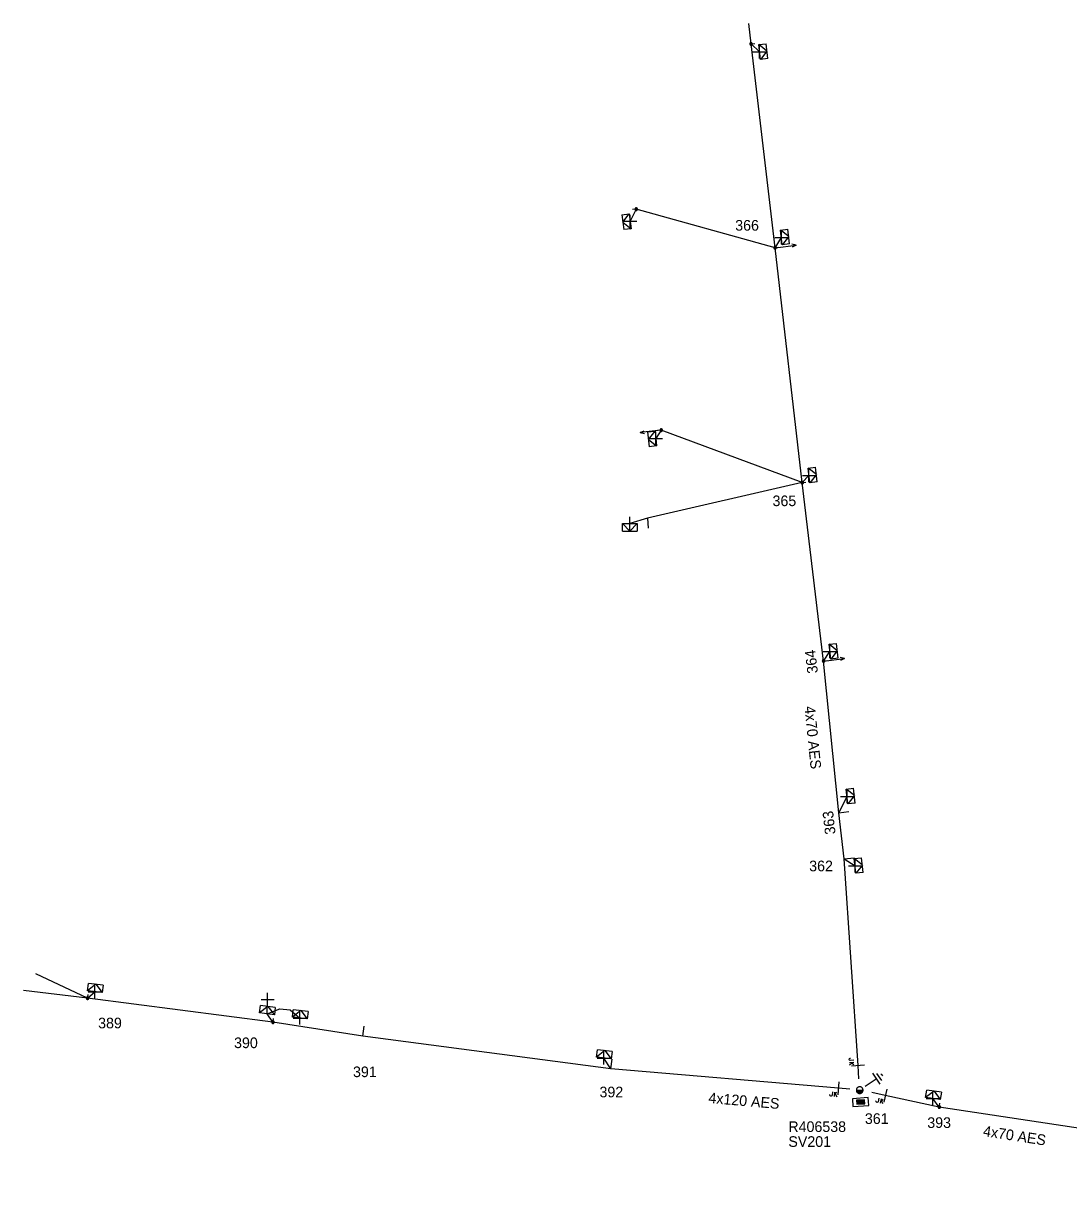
# Model space of a CAD drawing. Extents: x -540466 to -537383, y -1184038 to -1179972.
# Drawn here: x -539419.3 to -539321, y -1180540.1 to -1180429.3 of the extents above; entities that cross this region are included whole.
import ezdxf

# ---------------------------------------------------------------- set-up
doc = ezdxf.new("R2010")
doc.units = 0
for name, color, linetype in [('Vrstva 1', 7, 'Continuous'), ('Vrstva 13', 7, 'Continuous'), ('Vrstva 14', 7, 'Continuous'), ('Vrstva 15', 7, 'Continuous'), ('Vrstva 18', 7, 'Continuous'), ('Vrstva 2', 7, 'Continuous'), ('Vrstva 28', 7, 'Continuous'), ('Vrstva 29', 7, 'Continuous'), ('Vrstva 30', 7, 'Continuous'), ('Vrstva 31', 7, 'Continuous'), ('Vrstva 34', 7, 'Continuous'), ('Vrstva 50', 7, 'Continuous'), ('Vrstva 51', 7, 'Continuous'), ('Vrstva 54', 7, 'Continuous'), ('Vrstva 59', 7, 'Continuous'), ('Vrstva 8', 7, 'Continuous'), ('Vrstva 9', 7, 'Continuous')]:
    doc.layers.add(name, color=color, linetype=linetype)

# ---------------------------------------------------------------- blocks, each defined once
blk = doc.blocks.new('NN440')
at = {"layer": 'Vrstva 2'}
for points in [[(0.63, 0), (0.63, 0.06), (0.62, 0.13), (0.6, 0.19), (0.58, 0.25), (0.55, 0.31), (0.51, 0.37), (0.47, 0.42), (0.42, 0.46), (0.37, 0.51), (0.32, 0.54), (0.26, 0.57), (0.2, 0.59), (0.13, 0.61), (0.07, 0.62), (0, 0.63), (-0.06, 0.62), (-0.13, 0.61), (-0.19, 0.59), (-0.26, 0.57), (-0.31, 0.54), (-0.37, 0.51), (-0.42, 0.46), (-0.47, 0.42), (-0.51, 0.37), (-0.54, 0.31), (-0.57, 0.25), (-0.6, 0.19), (-0.62, 0.13), (-0.63, 0.06), (-0.63, 0), (-0.63, -0.07), (-0.62, -0.14), (-0.6, -0.2), (-0.57, -0.26), (-0.54, -0.32), (-0.51, -0.37), (-0.47, -0.43), (-0.42, -0.47), (-0.37, -0.51), (-0.31, -0.55), (-0.26, -0.58), (-0.19, -0.6), (-0.13, -0.62), (-0.06, -0.63), (0, -0.63), (0.07, -0.63), (0.13, -0.62), (0.2, -0.6), (0.26, -0.58), (0.32, -0.55), (0.37, -0.51), (0.42, -0.47), (0.47, -0.43), (0.51, -0.37), (0.55, -0.32), (0.58, -0.26), (0.6, -0.2), (0.62, -0.14), (0.63, -0.07), (0.63, 0)], [(-0.63, 0), (0.63, 0)], [(-0.6, -0.18), (0.57, -0.18)], [(-0.51, -0.32), (0.5, -0.32)], [(-0.37, -0.47), (0.35, -0.47)]]:
    blk.add_lwpolyline(points, dxfattribs=at)
blk = doc.blocks.new('NN560')
at = {"layer": 'Vrstva 2'}
for points in [[(2, 0), (1.59, 0.14)], [(0, 0), (2, 0)], [(2, 0), (1.59, -0.13)]]:
    blk.add_lwpolyline(points, dxfattribs=at)
blk = doc.blocks.new('NN840')
at = {"layer": 'Vrstva 15'}
for points in [[(0, 0.62), (0, -0.63)], [(-0.75, -0.71), (-0.75, -0.66)], [(-0.73, -0.76), (-0.75, -0.71)], [(-0.66, -0.8), (-0.73, -0.76)], [(-0.63, -0.8), (-0.66, -0.8)], [(-0.56, -0.76), (-0.63, -0.8)], [(-0.54, -0.71), (-0.56, -0.76)], [(-0.54, -0.38), (-0.54, -0.71)], [(-0.33, -0.38), (-0.33, -0.8)], [(-0.33, -0.64), (-0.13, -0.38)], [(-0.26, -0.56), (-0.09, -0.8)]]:
    blk.add_lwpolyline(points, dxfattribs=at)
blk = doc.blocks.new('NN800')
at = {"layer": 'Vrstva 1'}
for points in [[(-0.44, 0.44), (0.44, -0.44)], [(-0.44, -0.44), (0.44, 0.44)]]:
    blk.add_lwpolyline(points, dxfattribs=at)
blk = doc.blocks.new('NN620')
at = {"layer": 'Vrstva 8'}
for points in [[(0.75, 0), (-0.75, 0)], [(-0.75, 0), (-0.75, -0.75)], [(0.75, -0.75), (0.75, 0)], [(-0.75, -0.75), (0.75, -0.75)], [(0.37, -0.18), (-0.38, -0.18)], [(-0.38, -0.18), (-0.38, -0.56)], [(-0.38, -0.56), (0.37, -0.56)], [(0.32, -0.23), (-0.33, -0.23)], [(-0.33, -0.23), (-0.33, -0.51)], [(-0.33, -0.51), (0.32, -0.51)], [(0.27, -0.27), (-0.28, -0.27)], [(-0.28, -0.27), (-0.28, -0.46)], [(-0.28, -0.46), (0.27, -0.46)], [(0.23, -0.32), (-0.23, -0.32)], [(-0.23, -0.32), (-0.23, -0.42)], [(-0.23, -0.42), (0.23, -0.42)], [(-0.19, -0.37), (0.19, -0.37)], [(0.23, -0.42), (0.23, -0.32)], [(0.27, -0.46), (0.27, -0.27)], [(0.32, -0.51), (0.32, -0.23)], [(0.37, -0.56), (0.37, -0.18)]]:
    blk.add_lwpolyline(points, dxfattribs=at)
blk = doc.blocks.new('NN630')
at = {"layer": 'Vrstva 9'}
for points in [[(0, -0.7), (-0.7, 0)], [(-0.7, -0.7), (-0.7, 0), (0.7, 0), (0.7, -0.7)], [(-0.7, -0.7), (0.7, -0.7)], [(0, -0.7), (0.7, 0)]]:
    blk.add_lwpolyline(points, dxfattribs=at)
blk = doc.blocks.new('NN810')
at = {"layer": 'Vrstva 14'}
for points in [[(0, -0.64), (0, -1.89)], [(0.63, -1.89), (-0.62, -1.89)], [(0.39, -2.2), (-0.4, -2.2)], [(0, -2.52), (-0.12, -2.52)], [(0.14, -2.52), (0, -2.52)]]:
    blk.add_lwpolyline(points, dxfattribs=at)
blk = doc.blocks.new('NN500')
at = {"layer": 'Vrstva 2'}
for points in [[(0, -0.24), (0.02, -0.23), (0.05, -0.23), (0.07, -0.22), (0.09, -0.22), (0.12, -0.2), (0.14, -0.19), (0.16, -0.18), (0.17, -0.16), (0.19, -0.14), (0.2, -0.12), (0.21, -0.1), (0.22, -0.07), (0.23, -0.05), (0.23, -0.02), (0.23, 0), (0.23, 0.02), (0.23, 0.05), (0.22, 0.07), (0.21, 0.1), (0.2, 0.12), (0.19, 0.14), (0.17, 0.16), (0.16, 0.17), (0.14, 0.19), (0.12, 0.2), (0.09, 0.21), (0.07, 0.22), (0.05, 0.23), (0.02, 0.23), (0, 0.23), (-0.03, 0.23), (-0.05, 0.23), (-0.07, 0.22), (-0.1, 0.21), (-0.12, 0.2), (-0.14, 0.19), (-0.16, 0.17), (-0.18, 0.16), (-0.19, 0.14), (-0.2, 0.12), (-0.22, 0.1), (-0.22, 0.07), (-0.23, 0.05), (-0.23, 0.02), (-0.24, 0), (-0.23, -0.02), (-0.23, -0.05), (-0.22, -0.07), (-0.22, -0.1), (-0.2, -0.12), (-0.19, -0.14), (-0.18, -0.16), (-0.16, -0.18), (-0.14, -0.19), (-0.12, -0.2), (-0.1, -0.22), (-0.07, -0.22), (-0.05, -0.23), (-0.03, -0.23), (0, -0.24)], [(0, -0.24), (0.02, -0.23), (0.05, -0.23), (0.07, -0.22), (0.09, -0.22), (0.12, -0.2), (0.14, -0.19), (0.16, -0.18), (0.17, -0.16), (0.19, -0.14), (0.2, -0.12), (0.21, -0.1), (0.22, -0.07), (0.23, -0.05), (0.23, -0.02), (0.23, 0), (0.23, 0.02), (0.23, 0.05), (0.22, 0.07), (0.21, 0.1), (0.2, 0.12), (0.19, 0.14), (0.17, 0.16), (0.16, 0.17), (0.14, 0.19), (0.12, 0.2), (0.09, 0.21), (0.07, 0.22), (0.05, 0.23), (0.02, 0.23), (0, 0.23), (-0.03, 0.23), (-0.05, 0.23), (-0.07, 0.22), (-0.1, 0.21), (-0.12, 0.2), (-0.14, 0.19), (-0.16, 0.17), (-0.18, 0.16), (-0.19, 0.14), (-0.2, 0.12), (-0.22, 0.1), (-0.22, 0.07), (-0.23, 0.05), (-0.23, 0.02), (-0.24, 0), (-0.23, -0.02), (-0.23, -0.05), (-0.22, -0.07), (-0.22, -0.1), (-0.2, -0.12), (-0.19, -0.14), (-0.18, -0.16), (-0.16, -0.18), (-0.14, -0.19), (-0.12, -0.2), (-0.1, -0.22), (-0.07, -0.22), (-0.05, -0.23), (-0.03, -0.23), (0, -0.24)], [(0, -0.21), (0.02, -0.2), (0.04, -0.2), (0.06, -0.2), (0.08, -0.19), (0.1, -0.18), (0.12, -0.17), (0.14, -0.15), (0.15, -0.14), (0.16, -0.12), (0.18, -0.1), (0.19, -0.08), (0.19, -0.06), (0.2, -0.04), (0.2, -0.02), (0.2, 0), (0.2, 0.02), (0.2, 0.04), (0.19, 0.06), (0.19, 0.08), (0.18, 0.1), (0.16, 0.12), (0.15, 0.14), (0.14, 0.15), (0.12, 0.17), (0.1, 0.18), (0.08, 0.19), (0.06, 0.19), (0.04, 0.2), (0.02, 0.2), (0, 0.2), (-0.02, 0.2), (-0.04, 0.2), (-0.06, 0.19), (-0.08, 0.19), (-0.1, 0.18), (-0.12, 0.17), (-0.14, 0.15), (-0.15, 0.14), (-0.17, 0.12), (-0.18, 0.1), (-0.19, 0.08), (-0.2, 0.06), (-0.2, 0.04), (-0.21, 0.02), (-0.21, 0), (-0.21, -0.02), (-0.2, -0.04), (-0.2, -0.06), (-0.19, -0.08), (-0.18, -0.1), (-0.17, -0.12), (-0.15, -0.14), (-0.14, -0.15), (-0.12, -0.17), (-0.1, -0.18), (-0.08, -0.19), (-0.06, -0.2), (-0.04, -0.2), (-0.02, -0.2), (0, -0.21)], [(0, -0.18), (0.02, -0.18), (0.04, -0.17), (0.05, -0.17), (0.07, -0.16), (0.09, -0.15), (0.1, -0.14), (0.12, -0.13), (0.13, -0.12), (0.14, -0.1), (0.15, -0.09), (0.16, -0.07), (0.17, -0.05), (0.17, -0.04), (0.17, -0.02), (0.17, 0), (0.17, 0.02), (0.17, 0.04), (0.17, 0.05), (0.16, 0.07), (0.15, 0.09), (0.14, 0.1), (0.13, 0.12), (0.12, 0.13), (0.1, 0.14), (0.09, 0.15), (0.07, 0.16), (0.05, 0.17), (0.04, 0.17), (0.02, 0.17), (0, 0.18), (-0.02, 0.17), (-0.04, 0.17), (-0.06, 0.17), (-0.07, 0.16), (-0.09, 0.15), (-0.1, 0.14), (-0.12, 0.13), (-0.13, 0.12), (-0.14, 0.1), (-0.15, 0.09), (-0.16, 0.07), (-0.17, 0.05), (-0.17, 0.04), (-0.18, 0.02), (-0.18, 0), (-0.18, -0.02), (-0.17, -0.04), (-0.17, -0.05), (-0.16, -0.07), (-0.15, -0.09), (-0.14, -0.1), (-0.13, -0.12), (-0.12, -0.13), (-0.1, -0.14), (-0.09, -0.15), (-0.07, -0.16), (-0.06, -0.17), (-0.04, -0.17), (-0.02, -0.18), (0, -0.18)], [(0, -0.15), (0.01, -0.15), (0.03, -0.14), (0.04, -0.14), (0.06, -0.13), (0.07, -0.13), (0.08, -0.12), (0.1, -0.11), (0.11, -0.1), (0.12, -0.09), (0.13, -0.07), (0.13, -0.06), (0.14, -0.05), (0.14, -0.03), (0.14, -0.02), (0.14, 0), (0.14, 0.01), (0.14, 0.03), (0.14, 0.04), (0.13, 0.06), (0.13, 0.07), (0.12, 0.09), (0.11, 0.1), (0.1, 0.11), (0.08, 0.12), (0.07, 0.13), (0.06, 0.13), (0.04, 0.14), (0.03, 0.14), (0.01, 0.14), (0, 0.15), (-0.02, 0.14), (-0.03, 0.14), (-0.05, 0.14), (-0.06, 0.13), (-0.07, 0.13), (-0.09, 0.12), (-0.1, 0.11), (-0.11, 0.1), (-0.12, 0.09), (-0.13, 0.07), (-0.13, 0.06), (-0.14, 0.04), (-0.14, 0.03), (-0.15, 0.01), (-0.15, 0), (-0.15, -0.02), (-0.14, -0.03), (-0.14, -0.05), (-0.13, -0.06), (-0.13, -0.07), (-0.12, -0.09), (-0.11, -0.1), (-0.1, -0.11), (-0.09, -0.12), (-0.07, -0.13), (-0.06, -0.13), (-0.05, -0.14), (-0.03, -0.14), (-0.02, -0.15), (0, -0.15)], [(0, -0.12), (0.01, -0.12), (0.02, -0.11), (0.03, -0.11), (0.05, -0.11), (0.06, -0.1), (0.07, -0.09), (0.08, -0.09), (0.09, -0.08), (0.09, -0.07), (0.1, -0.06), (0.11, -0.05), (0.11, -0.04), (0.11, -0.02), (0.11, -0.01), (0.12, 0), (0.11, 0.01), (0.11, 0.02), (0.11, 0.04), (0.11, 0.05), (0.1, 0.06), (0.09, 0.07), (0.09, 0.08), (0.08, 0.09), (0.07, 0.09), (0.06, 0.1), (0.05, 0.11), (0.03, 0.11), (0.02, 0.11), (0.01, 0.12), (0, 0.12), (-0.01, 0.12), (-0.03, 0.11), (-0.04, 0.11), (-0.05, 0.11), (-0.06, 0.1), (-0.07, 0.09), (-0.08, 0.09), (-0.09, 0.08), (-0.1, 0.07), (-0.1, 0.06), (-0.11, 0.05), (-0.11, 0.04), (-0.12, 0.02), (-0.12, 0.01), (-0.12, 0), (-0.12, -0.01), (-0.12, -0.02), (-0.11, -0.04), (-0.11, -0.05), (-0.1, -0.06), (-0.1, -0.07), (-0.09, -0.08), (-0.08, -0.09), (-0.07, -0.09), (-0.06, -0.1), (-0.05, -0.11), (-0.04, -0.11), (-0.03, -0.11), (-0.01, -0.12), (0, -0.12)], [(0, -0.09), (0.01, -0.09), (0.02, -0.09), (0.03, -0.08), (0.03, -0.08), (0.04, -0.08), (0.05, -0.07), (0.06, -0.07), (0.06, -0.06), (0.07, -0.05), (0.07, -0.04), (0.08, -0.04), (0.08, -0.03), (0.08, -0.02), (0.09, -0.01), (0.09, 0), (0.09, 0.01), (0.08, 0.02), (0.08, 0.03), (0.08, 0.03), (0.07, 0.04), (0.07, 0.05), (0.06, 0.06), (0.06, 0.06), (0.05, 0.07), (0.04, 0.07), (0.03, 0.08), (0.03, 0.08), (0.02, 0.08), (0.01, 0.09), (0, 0.09), (-0.01, 0.09), (-0.02, 0.08), (-0.03, 0.08), (-0.04, 0.08), (-0.04, 0.07), (-0.05, 0.07), (-0.06, 0.06), (-0.07, 0.06), (-0.07, 0.05), (-0.08, 0.04), (-0.08, 0.03), (-0.08, 0.03), (-0.09, 0.02), (-0.09, 0.01), (-0.09, 0), (-0.09, -0.01), (-0.09, -0.02), (-0.08, -0.03), (-0.08, -0.04), (-0.08, -0.04), (-0.07, -0.05), (-0.07, -0.06), (-0.06, -0.07), (-0.05, -0.07), (-0.04, -0.08), (-0.04, -0.08), (-0.03, -0.08), (-0.02, -0.09), (-0.01, -0.09), (0, -0.09)], [(0, -0.06), (0, -0.06), (0.01, -0.06), (0.02, -0.05), (0.02, -0.05), (0.03, -0.05), (0.03, -0.05), (0.04, -0.04), (0.04, -0.04), (0.05, -0.03), (0.05, -0.03), (0.05, -0.02), (0.05, -0.02), (0.05, -0.01), (0.06, -0.01), (0.06, 0), (0.06, 0.01), (0.05, 0.01), (0.05, 0.02), (0.05, 0.02), (0.05, 0.03), (0.05, 0.03), (0.04, 0.04), (0.04, 0.04), (0.03, 0.05), (0.03, 0.05), (0.02, 0.05), (0.02, 0.05), (0.01, 0.06), (0, 0.06), (0, 0.06), (-0.01, 0.06), (-0.01, 0.06), (-0.02, 0.05), (-0.02, 0.05), (-0.03, 0.05), (-0.03, 0.05), (-0.04, 0.04), (-0.04, 0.04), (-0.05, 0.03), (-0.05, 0.03), (-0.05, 0.02), (-0.06, 0.02), (-0.06, 0.01), (-0.06, 0.01), (-0.06, 0), (-0.06, -0.01), (-0.06, -0.01), (-0.06, -0.02), (-0.05, -0.02), (-0.05, -0.03), (-0.05, -0.03), (-0.04, -0.04), (-0.04, -0.04), (-0.03, -0.05), (-0.03, -0.05), (-0.02, -0.05), (-0.02, -0.05), (-0.01, -0.06), (-0.01, -0.06), (0, -0.06)], [(0, -0.03), (0, -0.03), (0, -0.03), (0.01, -0.03), (0.01, -0.03), (0.01, -0.02), (0.02, -0.02), (0.02, -0.02), (0.02, -0.02), (0.02, -0.02), (0.02, -0.01), (0.02, -0.01), (0.03, -0.01), (0.03, -0.01), (0.03, 0), (0.03, 0), (0.03, 0), (0.03, 0.01), (0.03, 0.01), (0.02, 0.01), (0.02, 0.01), (0.02, 0.02), (0.02, 0.02), (0.02, 0.02), (0.02, 0.02), (0.01, 0.02), (0.01, 0.02), (0.01, 0.03), (0, 0.03), (0, 0.03), (0, 0.03), (0, 0.03), (-0.01, 0.03), (-0.01, 0.03), (-0.01, 0.02), (-0.02, 0.02), (-0.02, 0.02), (-0.02, 0.02), (-0.02, 0.02), (-0.02, 0.02), (-0.03, 0.01), (-0.03, 0.01), (-0.03, 0.01), (-0.03, 0.01), (-0.03, 0), (-0.03, 0), (-0.03, 0), (-0.03, -0.01), (-0.03, -0.01), (-0.03, -0.01), (-0.03, -0.01), (-0.02, -0.02), (-0.02, -0.02), (-0.02, -0.02), (-0.02, -0.02), (-0.02, -0.02), (-0.01, -0.03), (-0.01, -0.03), (-0.01, -0.03), (0, -0.03), (0, -0.03)], [(0.23, 0), (0.7, 0)]]:
    blk.add_lwpolyline(points, dxfattribs=at)
blk = doc.blocks.new('NN510')
at = {"layer": 'Vrstva 2'}
blk.add_lwpolyline([(0, 0), (0, 0.94)], dxfattribs=at)

msp = doc.modelspace()

# ---------------------------------------------------------------- linework, layer by layer
at = {"layer": 'Vrstva 50'}
for points in [[(-539340.71, -1180528.62), (-539340.79, -1180527.37), (-539342.1, -1180507.92), (-539342.59, -1180503.57), (-539344.04, -1180489.3), (-539346.04, -1180472.52), (-539348.6, -1180450.42), (-539350.86, -1180431.24), (-539351.08, -1180429.33)], [(-539341.58, -1180529.59), (-539342.64, -1180529.5), (-539364.05, -1180527.68), (-539387.39, -1180524.58), (-539395.84, -1180523.28), (-539413.28, -1180521.03), (-539419.31, -1180520.29)], [(-539295.49, -1180540.15), (-539317.17, -1180533.7), (-539333.15, -1180531.26), (-539338.23, -1180530.18), (-539339.49, -1180529.91)]]:
    msp.add_lwpolyline(points, dxfattribs=at)
at = {"layer": 'Vrstva 54'}
for points in [[(-539350.86, -1180431.24), (-539350.06, -1180432)], [(-539348.6, -1180450.42), (-539361.66, -1180446.79), (-539362.23, -1180447.93)], [(-539348.6, -1180450.42), (-539348.01, -1180449.45)], [(-539346.04, -1180472.52), (-539359.31, -1180467.58), (-539359.82, -1180468.36)], [(-539346.04, -1180472.52), (-539345.41, -1180471.84)], [(-539344.04, -1180489.3), (-539343.44, -1180488.42)], [(-539342.59, -1180503.57), (-539341.83, -1180502.05)], [(-539342.1, -1180507.92), (-539341.08, -1180508.58)], [(-539413.28, -1180521.03), (-539418.15, -1180518.74)], [(-539413.28, -1180521.03), (-539412.59, -1180520.41)], [(-539395.84, -1180523.28), (-539396.4, -1180522.5)], [(-539364.05, -1180527.68), (-539364.71, -1180526.65)], [(-539333.15, -1180531.26), (-539333.75, -1180530.46)]]:
    msp.add_lwpolyline(points, dxfattribs=at)
at = {"layer": 'Vrstva 59'}
for points in [[(-539396.4, -1180522.5), (-539396.34, -1180521.14)], [(-539396.4, -1180522.5), (-539395.2, -1180522.01), (-539394.23, -1180522.11), (-539393.32, -1180522.89)]]:
    msp.add_lwpolyline(points, dxfattribs=at)
at = {"layer": 'Vrstva 8'}
msp.add_lwpolyline([(-539346.04, -1180472.52), (-539360.59, -1180475.87), (-539362.27, -1180476.37)], dxfattribs=at)

# ---------------------------------------------------------------- block references
at = {"layer": 'Vrstva 13'}
for name, p, xscale, yscale, rotation in [('NN500', (-539350.86, -1180431.24), 0.5, 0.49999999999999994, 6.555000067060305), ('NN500', (-539361.66, -1180446.79), 0.5, 0.5, -172.94099985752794), ('NN500', (-539348.6, -1180450.42), 0.5, 0.5, 6.707999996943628), ('NN500', (-539359.31, -1180467.58), 0.5, 0.49999999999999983, -173.73599994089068), ('NN500', (-539346.04, -1180472.52), 0.49999999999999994, 0.4999999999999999, 6.7259999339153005), ('NN500', (-539344.04, -1180489.3), 0.5, 0.5000000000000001, 6.847999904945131), ('NN500', (-539413.28, -1180521.02), 0.49999999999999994, 0.5000000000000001, 82.75099996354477), ('NN500', (-539395.84, -1180523.28), 0.49999999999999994, 0.5000000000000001, 82.88200003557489), ('NN440', (-539340.64, -1180529.67), 0.5, 0.5, -0.06861404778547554), ('NN500', (-539333.15, -1180531.26), 0.5000000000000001, 0.4999999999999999, 81.30800001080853)]:
    msp.add_blockref(name, p, dxfattribs=dict(at, xscale=xscale, yscale=yscale, rotation=rotation))
for name, p, rotation in [('NN560', (-539348.6, -1180450.42), 6.708163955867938), ('NN560', (-539359.31, -1180467.58), -173.37659162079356), ('NN510', (-539360.59, -1180475.87), -176.12601395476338), ('NN560', (-539344.04, -1180489.3), 6.84837496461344), ('NN510', (-539342.59, -1180503.57), -83.4970583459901), ('NN510', (-539342.1, -1180507.91), -83.49705833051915), ('NN510', (-539387.39, -1180524.58), -7.2445054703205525), ('NN510', (-539364.05, -1180527.68), -7.356188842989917)]:
    msp.add_blockref(name, p, dxfattribs=dict(at, rotation=rotation))
at = {"layer": 'Vrstva 15', "rotation": 124.49032779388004}
msp.add_blockref('NN810', (-539340.64, -1180529.67), dxfattribs=at)
at = {"layer": 'Vrstva 18'}
for p, rotation in [((-539340.79, -1180527.37), -86.16957499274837), ((-539342.64, -1180529.5), -4.870599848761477), ((-539338.23, -1180530.18), -11.998547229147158)]:
    msp.add_blockref('NN840', p, dxfattribs=dict(at, rotation=rotation))
at = {"layer": 'Vrstva 28', "rotation": 4.48800004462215}
msp.add_blockref('NN620', (-539340.58, -1180530.42), dxfattribs=at)
at = {"layer": 'Vrstva 31'}
for p, rotation in [((-539350.06, -1180432), 96.55520831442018), ((-539362.23, -1180447.93), -82.94099159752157), ((-539348.01, -1180449.45), 96.70816388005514), ((-539359.82, -1180468.37), -83.73555276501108), ((-539345.41, -1180471.84), 96.72551664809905), ((-539362.27, -1180476.37), 0.008769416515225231), ((-539343.44, -1180488.42), 96.84837495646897), ((-539341.83, -1180502.05), 96.68931667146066), ((-539341.08, -1180508.58), 96.50294166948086), ((-539412.59, -1180520.41), 172.7509806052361), ((-539396.4, -1180522.5), 172.88195550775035), ((-539393.32, -1180522.89), 172.7554945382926), ((-539364.71, -1180526.65), 172.64381103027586), ((-539333.75, -1180530.46), 171.3081916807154)]:
    msp.add_blockref('NN630', p, dxfattribs=dict(at, rotation=rotation))
at = {"layer": 'Vrstva 34'}
for p, rotation in [((-539350.06, -1180432), 45), ((-539362.23, -1180447.93), 45), ((-539348.01, -1180449.45), 45.00000009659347), ((-539359.82, -1180468.37), 45), ((-539345.41, -1180471.84), 45), ((-539362.27, -1180476.37), 44.99999995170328), ((-539343.44, -1180488.42), 45), ((-539341.83, -1180502.05), 45.00000009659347), ((-539341.08, -1180508.58), 45), ((-539412.59, -1180520.41), 45), ((-539396.34, -1180521.14), 45.000000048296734), ((-539393.32, -1180522.89), 45), ((-539364.71, -1180526.65), 45), ((-539333.75, -1180530.46), 45)]:
    msp.add_blockref('NN800', p, dxfattribs=dict(at, rotation=rotation))

# ---------------------------------------------------------------- texts
at = {"layer": 'Vrstva 14'}
for s, p in [('366', (-539352.35, -1180448.81)), ('365', (-539348.84, -1180474.73)), ('362', (-539345.39, -1180509.08)), ('389', (-539412.29, -1180523.86)), ('390', (-539399.5, -1180525.72)), ('391', (-539388.31, -1180528.45)), ('392', (-539365.12, -1180530.35)), ('393', (-539334.28, -1180533.23))]:
    msp.add_text(s, height=1, dxfattribs=at).set_placement(p)
for s, rotation, p in [('364', 96.848, (-539344.56, -1180490.42)), ('363', 96.503, (-539342.9, -1180505.57)), ('361', 359.931, (-539340.15, -1180532.85))]:
    msp.add_text(s, height=1, rotation=rotation, dxfattribs=at).set_placement(p)
at = {"layer": 'Vrstva 29'}
msp.add_text('R406538', height=1, dxfattribs=at).set_placement((-539347.35, -1180533.61))
at = {"layer": 'Vrstva 30'}
msp.add_text('SV201', height=1, dxfattribs=at).set_placement((-539347.35, -1180535.01))
at = {"layer": 'Vrstva 51'}
for s, rotation, p in [('4x70 AES', 275.773, (-539345.84, -1180493.59)), ('4x120 AES', 355.13, (-539354.9, -1180530.88)), ('4x70 AES', 351.318, (-539329.08, -1180533.99))]:
    msp.add_text(s, height=1, rotation=rotation, dxfattribs=at).set_placement(p)

doc.saveas('drawing.dxf')
